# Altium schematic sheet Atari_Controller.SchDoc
size A3; SheetNumber: 1; SheetTotal: 1
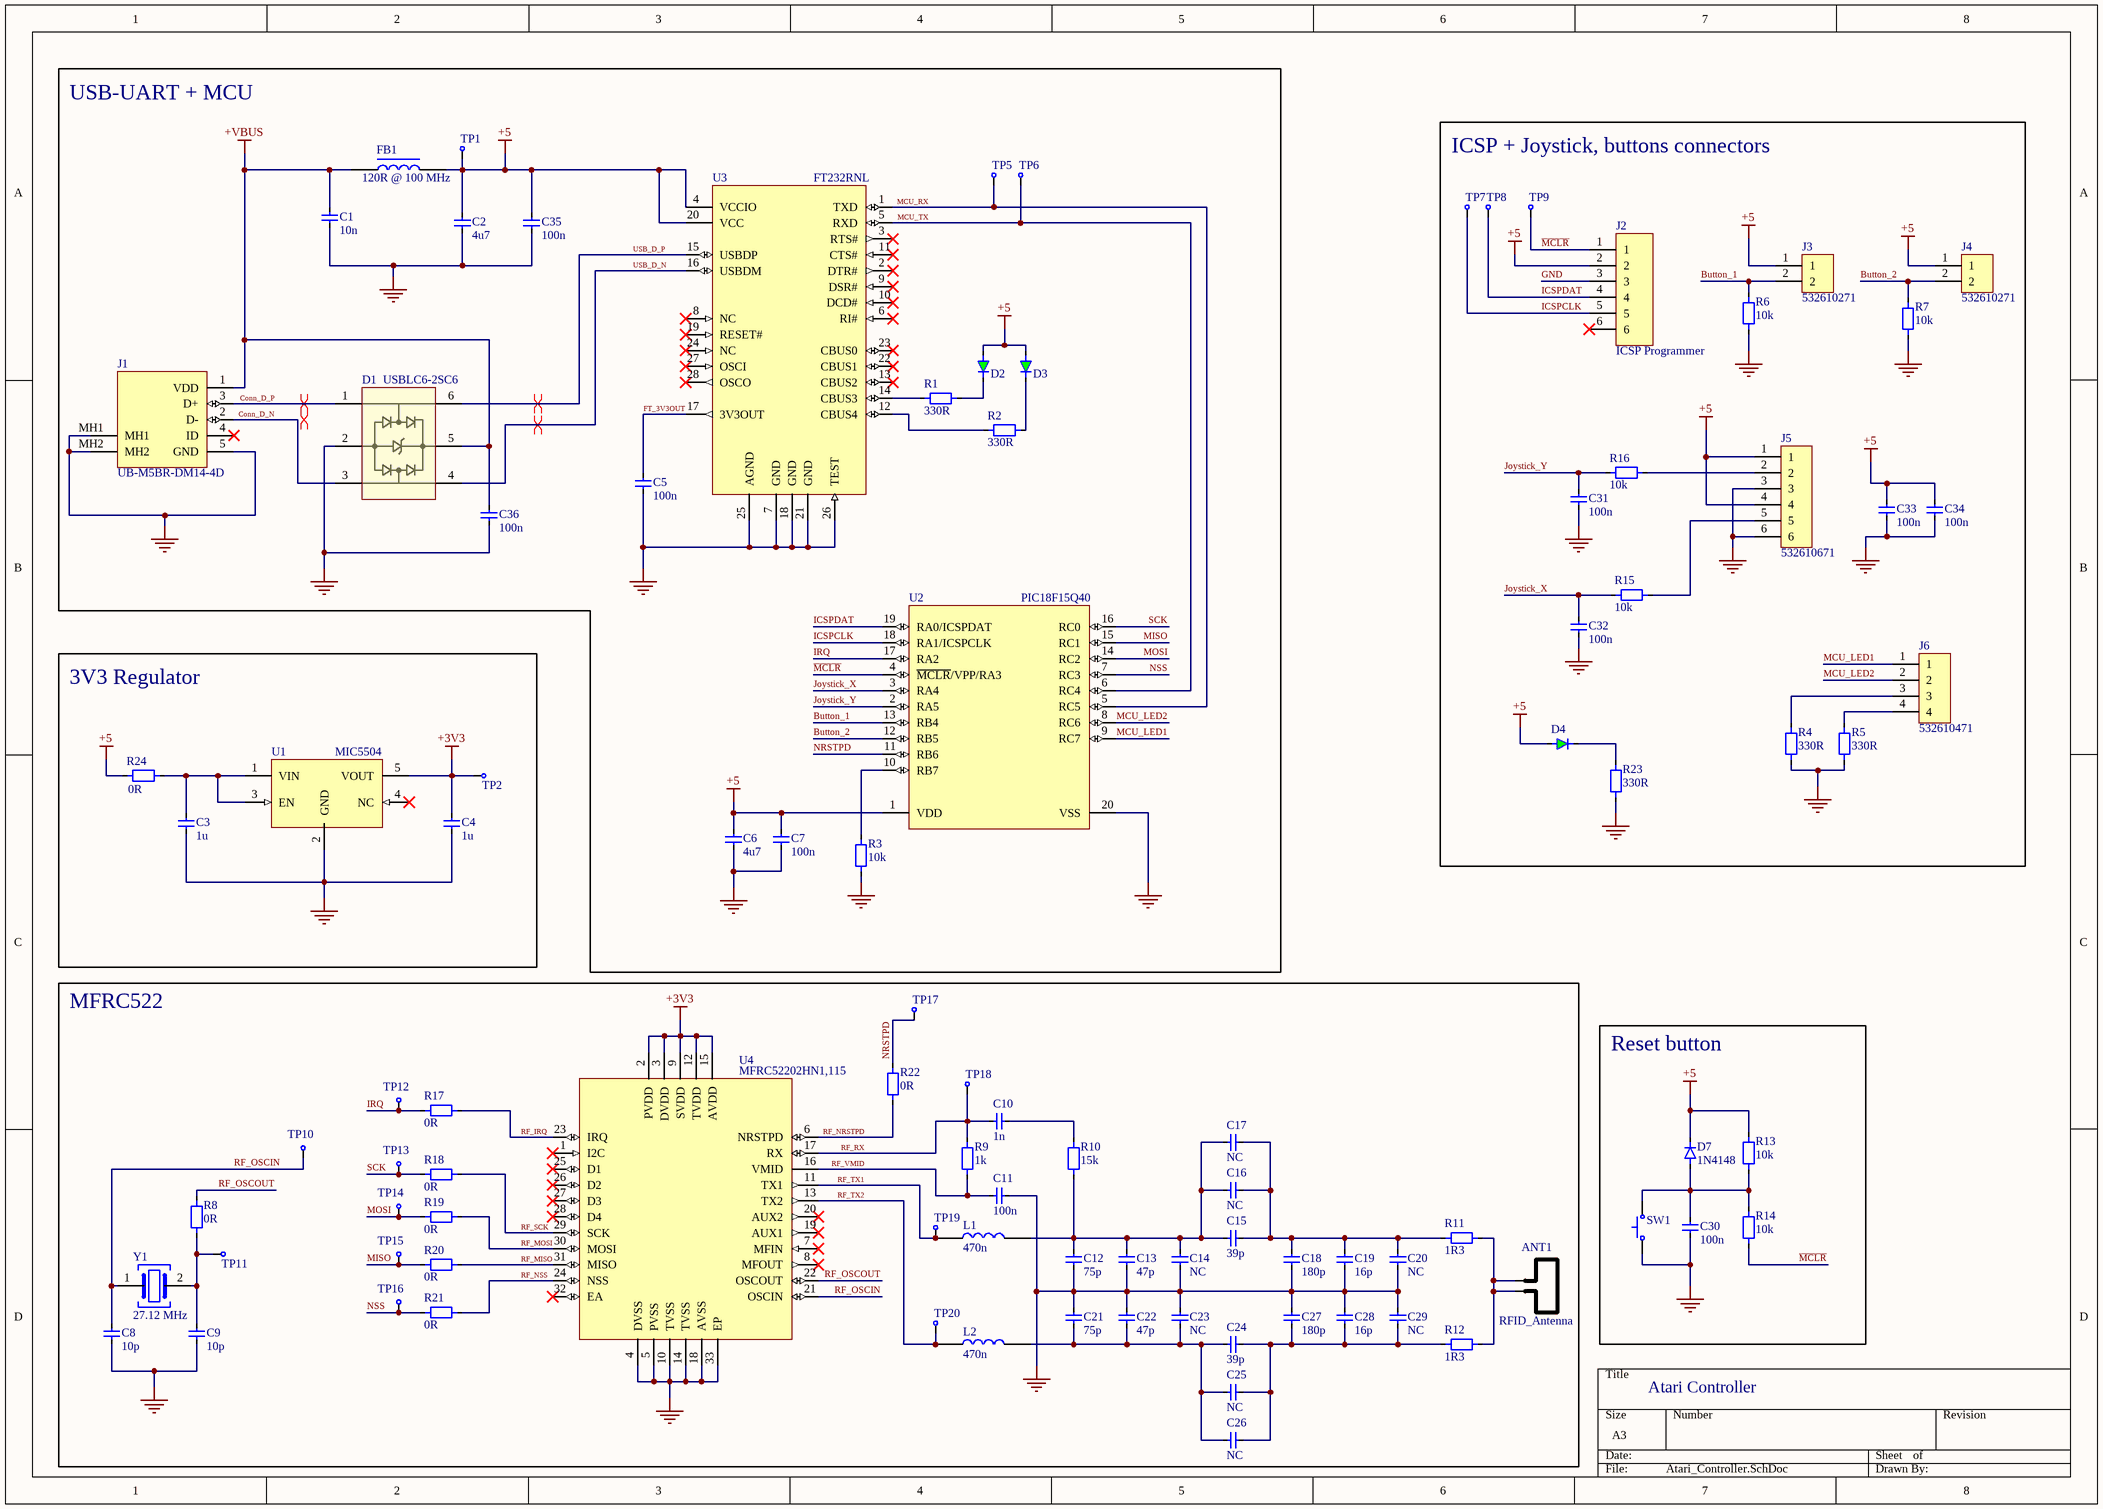
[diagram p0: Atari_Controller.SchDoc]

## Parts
ANT1  RFID_Antenna  [RFID_Antenna]
C1  10n  [CAP_0603]
C2  4u7  [CAP_0603]
C3  1u  [CAP_0603]
C4  1u  [CAP_0603]
C5  100n  [CAP_0603]
C6  4u7  [CAP_0603]
C7  100n  [CAP_0603]
C8  10p  [CAP_0603]
C9  10p  [CAP_0603]
C10  1n  [CAP_0603]
C11  100n  [CAP_0603]
C12  75p  [CAP_0603]
C13  47p  [CAP_0603]
C14  NC  [CAP_0603]
C15  39p  [CAP_0603]
C16  NC  [CAP_0603]
C17  NC  [CAP_0603]
C18  180p  [CAP_0603]
C19  16p  [CAP_0603]
C20  NC  [CAP_0603]
C21  75p  [CAP_0603]
C22  47p  [CAP_0603]
C23  NC  [CAP_0603]
C24  39p  [CAP_0603]
C25  NC  [CAP_0603]
C26  NC  [CAP_0603]
C27  180p  [CAP_0603]
C28  16p  [CAP_0603]
C29  NC  [CAP_0603]
C30  100n  [CAP_0603]
C31  100n  [CAP_0603]
C32  100n  [CAP_0603]
C33  100n  [CAP_0603]
C34  100n  [CAP_0603]
C35  100n  [CAP_0603]
C36  100n  [CAP_0603]
D1  USBLC6-2SC6  [SOT-666]
D2  SMD-GREEN  [LED_0603]  (value not drawn)
D3  SMD-GREEN  [LED_0603]  (value not drawn)
D4  SMD-RED  [LED_0603]  (value not drawn)
D7  1N4148  [1N4148]
FB1  120R @ 100 MHz  [Ferrite_Bead_0603]
J1  UB-M5BR-DM14-4D  [USB-B-MINI]
J2  ICSP Programmer  [6_pin_2.54]
J3  532610271  [Molex_Picoblade_2pin]
J4  532610271  [Molex_Picoblade_2pin]
J5  532610671  [Molex_Picoblade_6pin]
J6  532610471  [MOLEX_PICOBLADE_4Pin]
L1  470n  [IND_0603]
L2  470n  [IND_0603]
R1  330R  [RES_0603]
R2  330R  [RES_0603]
R3  10k  [RES_0603]
R4  330R  [RES_0603]
R5  330R  [RES_0603]
R6  10k  [RES_0603]
R7  10k  [RES_0603]
R8  0R  [RES_0603]
R9  1k  [RES_0603]
R10  15k  [RES_0603]
R11  1R3  [RES_0603]
R12  1R3  [RES_0603]
R13  10k  [RES_0603]
R14  10k  [RES_0603]
R15  10k  [RES_0603]
R16  10k  [RES_0603]
R17  0R  [RES_0603]
R18  0R  [RES_0603]
R19  0R  [RES_0603]
R20  0R  [RES_0603]
R21  0R  [RES_0603]
R22  0R  [RES_0603]
R23  330R  [RES_0603]
R24  0R  [RES_0603]
SW1  SPST_Switch  [Tactile_Switch_4.5x4.5]  (value not drawn)
TP1  TestPoint  [Pad_2.5mm]  (value not drawn)
TP2  TestPoint  [Pad_2.5mm]  (value not drawn)
TP5  TestPoint  [Pad_2.5mm]  (value not drawn)
TP6  TestPoint  [Pad_2.5mm]  (value not drawn)
TP7  TestPoint  [Pad_2.5mm]  (value not drawn)
TP8  TestPoint  [Pad_2.5mm]  (value not drawn)
TP9  TestPoint  [Pad_2.5mm]  (value not drawn)
TP10  TestPoint  [Pad_2.5mm]  (value not drawn)
TP11  TestPoint  [Pad_2.5mm]  (value not drawn)
TP12  TestPoint  [Pad_2.5mm]  (value not drawn)
TP13  TestPoint  [Pad_2.5mm]  (value not drawn)
TP14  TestPoint  [Pad_2.5mm]  (value not drawn)
TP15  TestPoint  [Pad_2.5mm]  (value not drawn)
TP16  TestPoint  [Pad_2.5mm]  (value not drawn)
TP17  TestPoint  [Pad_2.5mm]  (value not drawn)
TP18  TestPoint  [Pad_2.5mm]  (value not drawn)
TP19  TestPoint  [Pad_2.5mm]  (value not drawn)
TP20  TestPoint  [Pad_2.5mm]  (value not drawn)
U1  MIC5504  [SOT-23-5]
U2  PIC18F15Q40  [SOP20]
U3  FT232RNL  [SOP65P780X200-28N]
U4  MFRC52202HN1,115  [PQFN50P500X500X100_HS-33N]
Y1  27.12 MHz  [CrystalOscillator]

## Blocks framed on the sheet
USB-UART + MCU: C1 C2 C5-C7 C35 C36 D1-D3 FB1 J1 R1-R3 TP1 TP5 TP6 U2 U3
ICSP + Joystick, buttons connectors: C31-C34 D4 J2-J6 R4-R7 R15 R16 R23 TP7-TP9
3V3 Regulator: C3 C4 R24 TP2 U1
MFRC522: ANT1 C8-C29 L1 L2 R8-R12 R17-R22 TP10-TP20 U4 Y1
Reset button: C30 D7 R13 R14 SW1

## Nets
+3V3: C4.2 TP2.1 U1.5(VOUT) U4.2(PVDD) U4.3(DVDD) U4.9(SVDD) U4.12(TVDD) U4.15(AVDD)
+5: C2.2 C6.2 C7.2 C33.2 C34.2 C35.2 D2.2 D3.2 D4.2 D7.1 FB1.2 J2.2 J3.1 J4.1 J5.1 J5.4 R13.2 R24.1 TP1.1 U2.1(VDD) U3.4(VCCIO) U3.20(VCC)
+VBUS: C1.2 C36.2 D1.5(VBUS) FB1.1 J1.1(VDD)
GND: C1.1 C2.1 C3.1 C4.1 C5.1 C6.1 C7.1 C8.1 C9.1 C11.2 C12.1 C13.1 C14.1 C18.1 C19.1 C20.1 C21.2 C22.2 C23.2 C27.2 C28.2 C29.2 C30.1 C31.1 C32.1 C33.1 C34.1 C35.1 C36.1 D1.2(GND) J1.5(GND) J1.MH1 J1.MH2 J2.3 J5.3 J5.6 R3.1 R4.1 R5.1 R6.1 R7.1 R23.1 SW1.1 U1.2(GND) U2.20(VSS) U3.7(GND) U3.18(GND) U3.21(GND) U3.25(AGND) U3.26(TEST) U4.4(DVSS) U4.5(PVSS) U4.10(TVSS) U4.14(TVSS) U4.18(AVSS) U4.33(EP)
Button_1: J3.2 R6.2 U2.13(RB4)
Button_2: J4.2 R7.2 U2.12(RB5)
Conn_D_N: D1.3(I/O_2) J1.2(D-)
Conn_D_P: D1.1(I/O_1) J1.3(D+)
FT_3V3OUT: C5.2 U3.17(3V3OUT)
ICSPCLK: J2.5 TP7.1 U2.18(RA1/ICSPCLK)
ICSPDAT: J2.4 TP8.1 U2.19(RA0/ICSPDAT)
IRQ: R17.1 TP12.1 U2.17(RA2)
Joystick_X: C32.2 R15.1 U2.3(RA4)
Joystick_Y: C31.2 R16.1 U2.2(RA5)
~{MCLR}: J2.1 R14.1 TP9.1 U2.4(~{MCLR}/VPP/RA3)
MCU_LED1: J6.1 U2.9(RC7)
MCU_LED2: J6.2 U2.8(RC6)
MCU_RX: TP5.1 U2.5(RC5) U3.1(TXD)
MCU_TX: TP6.1 U2.6(RC4) U3.5(RXD)
MISO: R20.1 TP15.1 U2.15(RC1)
MOSI: R19.1 TP14.1 U2.14(RC2)
NRSTPD: R22.2 TP17.1 U2.11(RB6)
NSS: R21.1 TP16.1 U2.7(RC3)
RF_IRQ: R17.2 U4.23(IRQ)
RF_MISO: R20.2 U4.31(MISO)
RF_MOSI: R19.2 U4.30(MOSI)
RF_NRSTPD: R22.1 U4.6(NRSTPD)
RF_NSS: R21.2 U4.24(NSS)
RF_OSCIN: C8.2 TP10.1 U4.21(OSCIN) Y1.1
RF_OSCOUT: R8.2 U4.22(OSCOUT)
RF_RX: C10.2 R9.2 TP18.1 U4.17(RX)
RF_SCK: R18.2 U4.29(SCK)
RF_TX1: L1.1 TP19.1 U4.11(TX1)
RF_TX2: L2.1 TP20.1 U4.13(TX2)
RF_VMID: C11.1 R9.1 U4.16(VMID)
SCK: R18.1 TP13.1 U2.16(RC0)
USB_D_N: D1.4(I/O_3) U3.16(USBDM)
USB_D_P: D1.6(I/O_4) U3.15(USBDP)
NetANT1_1: ANT1.1 ANT1.2 R11.1 R12.2
NetC3_2: C3.2 R24.2 U1.1(VIN) U1.3(EN)
NetC9_2: C9.2 R8.1 TP11.1 Y1.2
NetC10_1: C10.1 R10.2
NetC12_2: C12.2 C13.2 C14.2 C15.1 C16.1 C17.1 L1.2 R10.1
NetC15_2: C15.2 C16.2 C17.2 C18.2 C19.2 C20.2 R11.2
NetC21_1: C21.1 C22.1 C23.1 C24.1 C25.1 C26.1 L2.2
NetC24_2: C24.2 C25.2 C26.2 C27.1 C28.1 C29.1 R12.1
NetC30_2: C30.2 D7.2 R13.1 R14.2 SW1.2
NetD2_1: D2.1 R1.2
NetD3_1: D3.1 R2.2
NetD4_1: D4.1 R23.2
NetJ5_2: J5.2 R16.2
NetJ5_5: J5.5 R15.2
NetJ6_3: J6.3 R4.2
NetJ6_4: J6.4 R5.2
NetR1_1: R1.1 U3.14(CBUS3)
NetR2_1: R2.1 U3.12(CBUS4)
NetR3_2: R3.2 U2.10(RB7)

Not connected (* = marked no-connect by the designer): J1 4(ID)*; J2 6*; U1 4(NC)*; U3 2(DTR#)* 3(RTS#)* 6(RI#)* 8(NC)* 9(DSR#)* 10(DCD#)* 11(CTS#)* 13(CBUS2)* 19(RESET#)* 22(CBUS1)* 23(CBUS0)* 24(NC)* 27(OSCI)* 28(OSCO)*; U4 1(I2C)* 7(MFIN)* 8(MFOUT)* 19(AUX1)* 20(AUX2)* 25(D1)* 26(D2)* 27(D3)* 28(D4)* 32(EA)*

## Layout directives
differential pair: Conn_D_N, Conn_D_P, USB_D_N, USB_D_P

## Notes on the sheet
- Atari Controller

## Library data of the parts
ANT1 = RFID_Antenna: Matching for MRFC522
C1-C4 C6-C29 C31-C34 C36 = CAP_0603_16V: Capacitor SMD 0603 16V
C5 C30 C35 = CAP_0603_10V: Capacitor SMD 0603 10V
D1 = USBLC6-2SC6: ESD Suppressors / TVS Diodes ESD Protection Low Cap
D2-D4 = LED_0603: LED SMD 0603
D7 = 1N4148: THT; 100V; 0,2A; Ifsm: 1A; DO35; Ufmax: 1V; 4ns
FB1 = FERRITE_BEAD_0603: Ferrite Bead 0603
J1 = USB-B-MINI
J2 = 6-pin header 2.54mm: 6 pin male header 2.54mm
J3 J4 = PicoBlade_2: Zásuvka; kabel-pl.spoj; vidlice; PicoBlade™; 1,25mm; PIN: 2; SMT; 1A
J5 = PicoBlade_6: Zásuvka; kabel-pl.spoj; vidlice; PicoBlade™; 1,25mm; PIN: 6; SMT; 1A
J6 = PicoBlade_4: Zásuvka; kabel-pl.spoj; vidlice; PicoBlade™; 1,25mm; PIN: 4; SMT; 1A
L1 L2 = IND_0603: Inductor 0603 SMD
R1-R24 = RES_0603: Resistor SMD 0603
SW1 = SPST_Switch: SPST-NO Tactile Switch 4.5x4.5
U1 = MIC5504-3.3YM5-TR: LDO regulator 3.3V
U2 = PIC18F15Q40: PIC18F04/05/14/15Q40 14/20-Pin, Low-Power, High-Performance Microcontroller
U3 = FT232RNL: USB Interface IC USB Full Speed to Serial UART IC, Includes Oscillator and EEPROM, SSOP-28
U4 = MFRC52202HN1,115: NFC/RFID Tags & Transponders Standard performance MIFARE and NTAG frontend
Y1 = Crystal_Oscillator: Crystal oscillator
